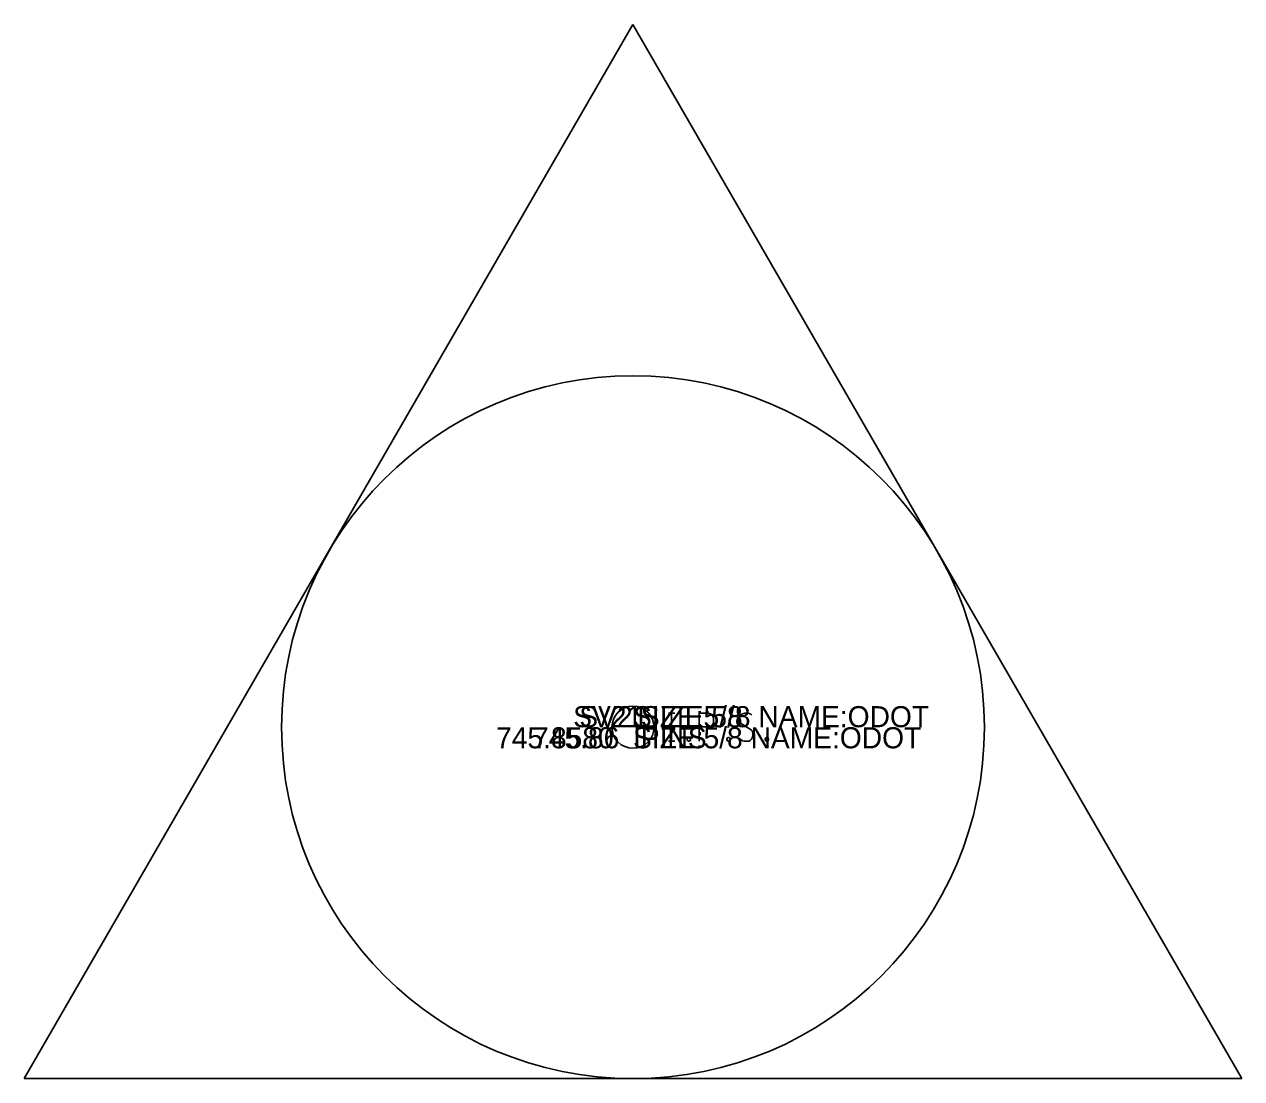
# Model space of a CAD drawing. Extents: x 1845019 to 1877956, y 680444 to 701081.
# Drawn here: x 1857804.762 to 1857808.226, y 694217.334 to 694220.334 of the extents above; entities that cross this region are included whole.
import ezdxf

# ---------------------------------------------------------------- set-up
doc = ezdxf.new("R2010")
doc.units = 0
for name, color, linetype in [('SV_Control_Point', 7, 'Continuous'), ('SV_P_Mon_Cells_Set', 7, 'Continuous'), ('SV_X_Text_Comment', 7, 'Continuous'), ('SV_X_Text_Description', 7, 'Continuous'), ('SV_X_Text_Elevation', 7, 'Continuous'), ('SV_X_Text_Name', 7, 'Continuous')]:
    doc.layers.add(name, color=color, linetype=linetype)

msp = doc.modelspace()

# ---------------------------------------------------------------- linework, layer by layer
at = {"layer": 'SV_Control_Point'}
for p, q in [((1857804.7623, 694217.3339), (1857806.4944, 694220.3339)), ((1857806.4944, 694220.3339), (1857808.2265, 694217.3339)), ((1857806.4944, 694218.3339), (1857806.4944, 694218.3339)), ((1857808.2265, 694217.3339), (1857804.7623, 694217.3339))]:
    msp.add_line(p, q, dxfattribs=at)
msp.add_circle((1857806.4944, 694218.3339), 1, dxfattribs=at)
at = {"layer": 'SV_P_Mon_Cells_Set'}
for points in [[(1857806.5953, 694218.374), (1857806.613, 694218.374)], [(1857806.5953, 694218.374), (1857806.613, 694218.374)], [(1857806.6042, 694218.294), (1857806.6042, 694218.374)], [(1857806.6042, 694218.294), (1857806.6042, 694218.374)], [(1857806.6824, 694218.294), (1857806.6824, 694218.374), (1857806.7089, 694218.374), (1857806.7116, 694218.3734), (1857806.7155, 694218.3721), (1857806.7172, 694218.3708), (1857806.7188, 694218.3696), (1857806.721, 694218.3664), (1857806.7227, 694218.3633), (1857806.7238, 694218.3582), (1857806.7238, 694218.3507), (1857806.7232, 694218.3482), (1857806.7221, 694218.3444), (1857806.7199, 694218.34), (1857806.7177, 694218.3381), (1857806.7161, 694218.3368), (1857806.7133, 694218.3356), (1857806.7089, 694218.3349), (1857806.6824, 694218.3349)], [(1857806.6824, 694218.294), (1857806.6824, 694218.374), (1857806.7089, 694218.374), (1857806.7116, 694218.3734), (1857806.7155, 694218.3721), (1857806.7172, 694218.3708), (1857806.7188, 694218.3696), (1857806.721, 694218.3664), (1857806.7227, 694218.3633), (1857806.7238, 694218.3582), (1857806.7238, 694218.3507), (1857806.7232, 694218.3482), (1857806.7221, 694218.3444), (1857806.7199, 694218.34), (1857806.7177, 694218.3381), (1857806.7161, 694218.3368), (1857806.7133, 694218.3356), (1857806.7089, 694218.3349), (1857806.6824, 694218.3349)], [(1857806.8329, 694218.3683), (1857806.8318, 694218.3696), (1857806.8301, 694218.3708), (1857806.8252, 694218.3727), (1857806.8191, 694218.374), (1857806.8147, 694218.374), (1857806.8131, 694218.374), (1857806.8059, 694218.3721), (1857806.7998, 694218.3683), (1857806.796, 694218.3633), (1857806.7949, 694218.3582), (1857806.7949, 694218.3545), (1857806.796, 694218.3494), (1857806.8004, 694218.345), (1857806.8307, 694218.3261), (1857806.8334, 694218.3236), (1857806.8345, 694218.3211), (1857806.8356, 694218.3173), (1857806.8356, 694218.3135), (1857806.8351, 694218.3097), (1857806.8345, 694218.3072), (1857806.8334, 694218.3041), (1857806.8323, 694218.3016), (1857806.8312, 694218.2997), (1857806.8296, 694218.2978), (1857806.8279, 694218.2965), (1857806.8257, 694218.2953), (1857806.8241, 694218.2946), (1857806.8191, 694218.294), (1857806.8114, 694218.294), (1857806.8064, 694218.2953), (1857806.7993, 694218.2997), (1857806.7949, 694218.3034)], [(1857806.8329, 694218.3683), (1857806.8318, 694218.3696), (1857806.8301, 694218.3708), (1857806.8252, 694218.3727), (1857806.8191, 694218.374), (1857806.8147, 694218.374), (1857806.8131, 694218.374), (1857806.8059, 694218.3721), (1857806.7998, 694218.3683), (1857806.796, 694218.3633), (1857806.7949, 694218.3582), (1857806.7949, 694218.3545), (1857806.796, 694218.3494), (1857806.8004, 694218.345), (1857806.8307, 694218.3261), (1857806.8334, 694218.3236), (1857806.8345, 694218.3211), (1857806.8356, 694218.3173), (1857806.8356, 694218.3135), (1857806.8351, 694218.3097), (1857806.8345, 694218.3072), (1857806.8334, 694218.3041), (1857806.8323, 694218.3016), (1857806.8312, 694218.2997), (1857806.8296, 694218.2978), (1857806.8279, 694218.2965), (1857806.8257, 694218.2953), (1857806.8241, 694218.2946), (1857806.8191, 694218.294), (1857806.8114, 694218.294), (1857806.8064, 694218.2953), (1857806.7993, 694218.2997), (1857806.7949, 694218.3034)], [(1857806.6521, 694218.3047), (1857806.6549, 694218.3047), (1857806.6565, 694218.3034), (1857806.6582, 694218.3009), (1857806.6582, 694218.2978), (1857806.6565, 694218.2953), (1857806.6549, 694218.294), (1857806.6521, 694218.294), (1857806.6505, 694218.2953), (1857806.6488, 694218.2978), (1857806.6488, 694218.3009), (1857806.6505, 694218.3034), (1857806.6521, 694218.3047)], [(1857806.6521, 694218.3047), (1857806.6549, 694218.3047), (1857806.6565, 694218.3034), (1857806.6582, 694218.3009), (1857806.6582, 694218.2978), (1857806.6565, 694218.2953), (1857806.6549, 694218.294), (1857806.6521, 694218.294), (1857806.6505, 694218.2953), (1857806.6488, 694218.2978), (1857806.6488, 694218.3009), (1857806.6505, 694218.3034), (1857806.6521, 694218.3047)], [(1857806.7646, 694218.3047), (1857806.7673, 694218.3047), (1857806.769, 694218.3034), (1857806.7706, 694218.3009), (1857806.7706, 694218.2978), (1857806.769, 694218.2953), (1857806.7673, 694218.294), (1857806.7646, 694218.294), (1857806.7629, 694218.2953), (1857806.7612, 694218.2978), (1857806.7612, 694218.3009), (1857806.7629, 694218.3034), (1857806.7646, 694218.3047)], [(1857806.7646, 694218.3047), (1857806.7673, 694218.3047), (1857806.769, 694218.3034), (1857806.7706, 694218.3009), (1857806.7706, 694218.2978), (1857806.769, 694218.2953), (1857806.7673, 694218.294), (1857806.7646, 694218.294), (1857806.7629, 694218.2953), (1857806.7612, 694218.2978), (1857806.7612, 694218.3009), (1857806.7629, 694218.3034), (1857806.7646, 694218.3047)], [(1857806.8737, 694218.3047), (1857806.8764, 694218.3047), (1857806.8781, 694218.3034), (1857806.8797, 694218.3009), (1857806.8797, 694218.2978), (1857806.8781, 694218.2953), (1857806.8764, 694218.294), (1857806.8737, 694218.294), (1857806.872, 694218.2953), (1857806.8704, 694218.2978), (1857806.8704, 694218.3009), (1857806.872, 694218.3034), (1857806.8737, 694218.3047)], [(1857806.8737, 694218.3047), (1857806.8764, 694218.3047), (1857806.8781, 694218.3034), (1857806.8797, 694218.3009), (1857806.8797, 694218.2978), (1857806.8781, 694218.2953), (1857806.8764, 694218.294), (1857806.8737, 694218.294), (1857806.872, 694218.2953), (1857806.8704, 694218.2978), (1857806.8704, 694218.3009), (1857806.872, 694218.3034), (1857806.8737, 694218.3047)], [(1857806.5953, 694218.294), (1857806.613, 694218.294)], [(1857806.5953, 694218.294), (1857806.613, 694218.294)]]:
    msp.add_lwpolyline(points, dxfattribs=at)
msp.add_circle((1857806.4944, 694218.3339), 0.06, dxfattribs=at)
msp.add_circle((1857806.4944, 694218.3339), 0.06, dxfattribs=at)

# ---------------------------------------------------------------- texts
at = {"layer": 'SV_X_Text_Comment'}
for s in ['SIZE:5/8 NAME:ODOT', 'IPINS']:
    msp.add_text(s, height=0.06, dxfattribs=at).set_placement((1857806.4944, 694218.2739))
at = {"layer": 'SV_X_Text_Description'}
for s in ['SIZE:5/8  NAME:ODOT', ' SIZE:5/8 NAME:ODOT']:
    msp.add_text(s, height=0.06, dxfattribs=at).set_placement((1857806.4944, 694218.3339))
at = {"layer": 'SV_X_Text_Elevation'}
for s, p in [('745.8580', (1857806.1047, 694218.2739)), ('745.86', (1857806.21, 694218.2739))]:
    msp.add_text(s, height=0.06, dxfattribs=at).set_placement(p)
at = {"layer": 'SV_X_Text_Name'}
for p in [(1857806.3242, 694218.3339), (1857806.3416, 694218.3339)]:
    msp.add_text('SV21', height=0.06, dxfattribs=at).set_placement(p)

doc.saveas('drawing.dxf')
